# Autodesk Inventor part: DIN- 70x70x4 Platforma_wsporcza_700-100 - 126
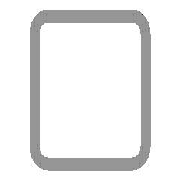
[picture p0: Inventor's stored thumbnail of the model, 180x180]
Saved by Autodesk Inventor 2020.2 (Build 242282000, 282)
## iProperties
Manager: www.cadconsulting.pl
Company: Fabian Stasiak CAD Consulting
_CCFamilyMember: 40
_CCFamilyDisplayName: DIN 59410 (Kwadrat) - Rurki stalowe o przekroju kwadratowym formowane na gorąco
_FrameMemberDoc: Frame Member File
_Version: 15.0.0
_GetPNFromCC: 1
IsCustomPart: 1
Created: 2014-02
Part Number: DIN- 70x70x4 Platforma_wsporcza_700-100 - 126
Material: Stal, miękka
Description: Rurki stalowe o przekroju kwadratowym formowane na gorąco
Document SubType Name: Modellieren
Standard: DIN
Designer: F.Stasiak
Standards Organization: DIN
Language: pl-PL
Size Designation: 50x50x4
Categories: <MemberInstance><Categories><Category DisplayName="Kształtowniki konstrukcyjne" InternalName="089c4875-fa83-4c05-b084-43b9cc11f5ed" Mnemonic="GRDR"><CategoryPar
Stock Number: 50x50x4
Density: 7.85 g/cm^3
Appearance: Częściowo polerowana
Mass: 13908.1 g
Surface Area: 8872.55 cm^2
Volume: 1771.73 cm^3
Catalog Web Link: www.expertbooks.pl
G_W: 50,000 mm
G_H: 50,000 mm
G_L: 2550,000 mm
+863FC32D-3A42-4B87-B9D3-D271F46AB554+CUTDETAIL3: Wytnij
+2CF58936-3DC0-4850-BAAD-E90BCFB07CED+CUTDETAIL4: Wytnij
Author: F.Stasiak
Subject: Zbiór ćwiczeń. Autodesk Inventor 2020. Kurs Professional
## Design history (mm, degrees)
node "Płaszczyzna początkowa"
node "Płaszczyzna końcowa"
sketch "Szkic1"
  geometry: L1 (-17, 25)-(17, 25); L2 (25, 17)-(25, -17); L3 (17, -25)-(-17, -25); L4 (-25, -17)-(-25, 17); L5 (-51.32, 0)-(51.32, 0) reference; L6 (0, -51.32)-(0, 51.32) reference; L7 (-17, 21)-(17, 21); L8 (21, 17)-(21, -17); L9 (17, -21)-(-17, -21); L10 (-21, -17)-(-21, 17); A1 r 8 centre (-17, 17) between (-17, 25) and (-25, 17); A2 r 8 centre (17, 17) between (25, 17) and (17, 25); A3 r 8 centre (17, -17) between (17, -25) and (25, -17); A4 r 8 centre (-17, -17) between (-25, -17) and (-17, -25); A5 r 4 centre (-17, 17) between (-17, 21) and (-21, 17); A6 r 4 centre (17, 17) between (21, 17) and (17, 21); A7 r 4 centre (17, -17) between (17, -21) and (21, -17); A8 r 4 centre (-17, -17) between (-21, -17) and (-17, -21); 3 further points
  constraints: 16 end point, 16 point on circle, 8 centre point, 8 tangent, 6 point on line, 4 parallel, 3 equal radius, 3 perpendicular, 1 horizontal, 7 other
  dimensions: "b" = 50 distance of point (-25, 25) point (25, 25); "msp_r" = 8 radius of A1 (= 2 x ParT); "d8" = 25 distance between parallel lines of L4 L6 (= d9); "d9" = 25 distance between parallel lines of L3 L5 (= 0.5 x b); "d10" = 4 distance between parallel lines of L3 L9 (= ParT)
extrude "Bryła" new body sketch "Szkic1" taper "d4" = 0 deg; stored distance "NLG" = 10
node "Driven Length"
  sketch "Sketch2"
    geometry: L1 (0, 0)-(10, 0) reference
    constraints: 2 end point, 1 horizontal
  workplane "Work Plane3"
  sketch "Sketch3"
    geometry: L1 (-2, -25)-(12, -25) reference; L2 (-2, 2525)-(12, 2525) reference
    dimensions: "d14" = 2550 distance between parallel lines of L1 L2 (derived)
node "Płaszczyzna konstrukcyjna6"
feature "Podział3"
node "Płaszczyzna konstrukcyjna7"
feature "Podział4"
body "Solid1"
other parameters: "ParT" = 4, "G_OFFSET_START" = 25 [user parameter; used in 1 equation term], "G_OFFSET_END" = 25 [user parameter; used in 1 equation term], "d11" = -25 (= -G_OFFSET_START), "d12" = 2525 (= G_OFFSET_END + B_L), "G_L" = 2550 (= d14) [user parameter], "d13" = 90 deg
